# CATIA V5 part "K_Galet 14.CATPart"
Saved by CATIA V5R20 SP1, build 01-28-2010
Part number: Galet 14
Bounding box of the stored display mesh (mm): x -66 to 66, y -19 to 19, z -65.991 to 65.991
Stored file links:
  G:\Khaled_CFAO_2011\SIL\SIL_GR1\gperrin\Khaled\CAD_CATIA\Khaled\K_Galet 14.CATPart
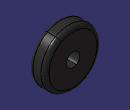
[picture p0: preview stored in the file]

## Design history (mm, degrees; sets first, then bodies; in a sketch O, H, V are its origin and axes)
Body1 (main body)
  Sketch1 on yz-plane, origin (0, 0, 0), H (0, 1, 0), V (0, 0, 1)
    line L1 (19, 16) -> (19, 56.5)
    line L2 (9.5, 66) -> (-9.5, 66)
    line L3 (-19, 56.5) -> (-19, 16)
    arc A1 centre (9.5, 56.5) radius 9.5 from (19, 56.5) to (9.5, 66) ccw
    arc A2 centre (-9.5, 56.5) radius 9.5 from (-19, 56.5) to (-9.5, 66) cw
    line L4 (-19, 16) -> (19, 16)
    axis line L5 (-36, 0) -> (89, 0)
    point P9 (-36, 0)
    radius A1 = 9.5
    radius A2 = 9.5
    distance L4 O = 16
    distance L2 L4 = 50
    length L4 = 38
    horizontal: L2 H, L4 H, L5 H
    vertical: L1 V, L3 V
    tangency: A1 L1, A1 L2, A2 L3, A2 L2
    coincidence: P9 H
  Shaft1: profile Sketch1, axis Sketch1.L5, angle 360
